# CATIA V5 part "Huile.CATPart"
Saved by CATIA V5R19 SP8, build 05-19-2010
Part number: Volume d'huile
Bounding box of the stored display mesh (mm): x -5.773 to 5.773, y -5.763 to 5.763, z -169.7 to 0
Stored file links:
  D:\Documents\1_Travail\1 - ac-limoges.fr\OneDrive - ac-limoges.fr\STI2D_Turgot\2 -2I2D\3_SEQUENCE_Serre_Connectée\3- Spécificités\ITEC\EC 3 Ouverture automatique\Vérin_Thermodynamique\Huile.CATPart
  D:\Documents\1_Travail\1 - ac-limoges.fr\ac-limoges.fr\Emmanuel Maynard - STI2D_Turgot\2 -2I2D\3_SEQUENCE_Serre_Connectée\Dossier technique_SERRE\Maquettes_CATIA\Vérin_Thermodynamique\Verin thermodynamique.CATProduct
  D:\Documents\1_Travail\1 - ac-limoges.fr\OneDrive - ac-limoges.fr\STI2D_Turgot\2 -2I2D\3_SEQUENCE_Serre_Connectée\3- Spécificités\ITEC\EC 3 Ouverture automatique\Vérin_Thermodynamique\Tete_de_verin.CATPart
  D:\Documents\1_Travail\1 - ac-limoges.fr\OneDrive - ac-limoges.fr\STI2D_Turgot\2 -2I2D\3_SEQUENCE_Serre_Connectée\3- Spécificités\ITEC\EC 3 Ouverture automatique\Vérin_Thermodynamique\Tige_de_verin.CATPart
  D:\Documents\1_Travail\1 - ac-limoges.fr\OneDrive - ac-limoges.fr\STI2D_Turgot\2 -2I2D\3_SEQUENCE_Serre_Connectée\3- Spécificités\ITEC\EC 3 Ouverture automatique\Vérin_Thermodynamique\0-Verin thermodynamique.CATProduct
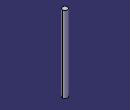
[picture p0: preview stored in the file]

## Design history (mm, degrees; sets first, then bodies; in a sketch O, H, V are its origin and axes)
AxisSystem1: origin (0, 0, 0), X (1, 0, 0), Y (0, 1, 0), Z (0, 0, 1)
Set1
  DatumSurface1
Body1 (main body)
  Sketch1 on XY plane of AxisSystem1, origin (0, 0, 0), H (1, 0, 0), V (0, 1, 0)
    circle A1 centre (0, 0) radius 5.773
    radius A1 = 5.773
  Pad1: profile Sketch1, direction (0, 0, 1), up to face of DatumSurface1
  Body2 "NONE"
    Solid1: linked copy from another document
  Remove1: tool Body2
